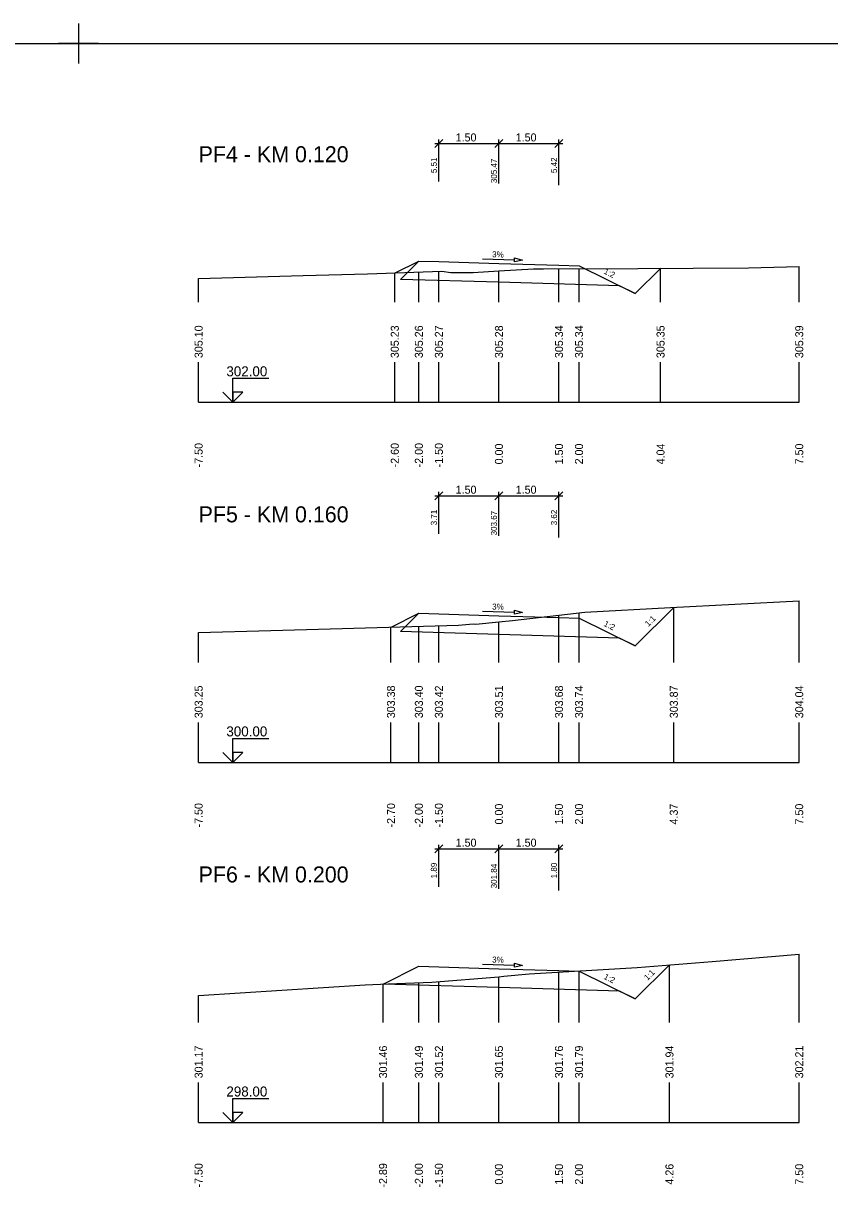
# Model space of a CAD drawing. Extents: x -5 to 1265, y -2 to 602.
# Drawn here: x 196.3 to 397.5, y 307.8 to 601.7 of the extents above; entities that cross this region are included whole.
import ezdxf

# ---------------------------------------------------------------- set-up
doc = ezdxf.new("R2010")
doc.units = 0
for name, color, linetype in [('KOTA', 7, 'Continuous'), ('KOTA_DELKY', 7, 'Continuous'), ('KOTA_DELKY_CONT', 7, 'Continuous'), ('NS_TELESO_VOZOVKY', 7, 'Continuous'), ('NS_V_PF', 7, 'Continuous'), ('REZY_PF_PUVODNI', 7, 'Continuous'), ('SESTAVY_REZU_PF', 7, 'Continuous'), ('SKLON', 7, 'Continuous'), ('SVK', 7, 'Continuous')]:
    doc.layers.add(name, color=color, linetype=linetype)

msp = doc.modelspace()

# ---------------------------------------------------------------- linework, layer by layer
for p, q in [((210, 601.67), (210, 591.67)), ((210, 601.67), (210, 591.67)), ((210, 601.67), (210, 591.67)), ((210, 601.67), (210, 591.67)), ((210, 601.67), (210, 591.67)), ((210, 601.67), (210, 591.67)), ((210, 601.67), (210, 591.67)), ((210, 601.67), (210, 591.67)), ((210, 601.67), (210, 591.67)), ((210, 601.67), (210, 591.67)), ((210, 601.67), (210, 591.67)), ((210, 601.67), (210, 591.67)), ((210, 601.67), (210, 591.67)), ((210, 601.67), (210, 591.67)), ((210, 601.67), (210, 591.67)), ((210, 601.67), (210, 591.67)), ((210, 601.67), (210, 591.67)), ((210, 601.67), (210, 591.67)), ((210, 601.67), (210, 591.67)), ((210, 601.67), (210, 591.67)), ((210, 601.67), (210, 591.67)), ((210, 601.67), (210, 591.67)), ((210, 601.67), (210, 591.67)), ((210, 601.67), (210, 591.67)), ((210, 601.67), (210, 591.67)), ((210, 601.67), (210, 591.67)), ((210, 601.67), (210, 591.67)), ((210, 601.67), (210, 591.67)), ((210, 601.67), (210, 591.67)), ((210, 601.67), (210, 591.67)), ((210, 601.67), (210, 591.67)), ((210, 601.67), (210, 591.67)), ((210, 601.67), (210, 591.67)), ((210, 601.67), (210, 591.67)), ((210, 601.67), (210, 591.67)), ((210, 601.67), (210, 591.67)), ((210, 601.67), (210, 591.67)), ((210, 601.67), (210, 591.67)), ((210, 601.67), (210, 591.67)), ((210, 601.67), (210, 591.67)), ((210, 601.67), (210, 591.67)), ((210, 601.67), (210, 591.67)), ((210, 601.67), (210, 591.67)), ((210, 601.67), (210, 591.67)), ((210, 601.67), (210, 591.67)), ((210, 601.67), (210, 591.67)), ((210, 601.67), (210, 591.67)), ((210, 601.67), (210, 591.67)), ((210, 601.67), (210, 591.67)), ((210, 601.67), (210, 591.67)), ((210, 601.67), (210, 591.67)), ((210, 601.67), (210, 591.67)), ((210, 601.67), (210, 591.67)), ((210, 601.67), (210, 591.67)), ((215, 596.67), (205, 596.67)), ((215, 596.67), (205, 596.67)), ((215, 596.67), (205, 596.67)), ((215, 596.67), (205, 596.67)), ((215, 596.67), (205, 596.67)), ((215, 596.67), (205, 596.67)), ((215, 596.67), (205, 596.67)), ((215, 596.67), (205, 596.67)), ((215, 596.67), (205, 596.67)), ((215, 596.67), (205, 596.67)), ((215, 596.67), (205, 596.67)), ((215, 596.67), (205, 596.67)), ((215, 596.67), (205, 596.67)), ((215, 596.67), (205, 596.67)), ((215, 596.67), (205, 596.67)), ((215, 596.67), (205, 596.67)), ((215, 596.67), (205, 596.67)), ((215, 596.67), (205, 596.67)), ((215, 596.67), (205, 596.67)), ((215, 596.67), (205, 596.67)), ((215, 596.67), (205, 596.67)), ((215, 596.67), (205, 596.67)), ((215, 596.67), (205, 596.67)), ((215, 596.67), (205, 596.67)), ((215, 596.67), (205, 596.67)), ((215, 596.67), (205, 596.67)), ((215, 596.67), (205, 596.67)), ((215, 596.67), (205, 596.67)), ((215, 596.67), (205, 596.67)), ((215, 596.67), (205, 596.67)), ((215, 596.67), (205, 596.67)), ((215, 596.67), (205, 596.67)), ((215, 596.67), (205, 596.67)), ((215, 596.67), (205, 596.67)), ((215, 596.67), (205, 596.67)), ((215, 596.67), (205, 596.67)), ((215, 596.67), (205, 596.67)), ((215, 596.67), (205, 596.67)), ((215, 596.67), (205, 596.67)), ((215, 596.67), (205, 596.67)), ((215, 596.67), (205, 596.67)), ((215, 596.67), (205, 596.67)), ((215, 596.67), (205, 596.67)), ((215, 596.67), (205, 596.67)), ((215, 596.67), (205, 596.67)), ((215, 596.67), (205, 596.67)), ((215, 596.67), (205, 596.67)), ((215, 596.67), (205, 596.67)), ((215, 596.67), (205, 596.67)), ((215, 596.67), (205, 596.67)), ((215, 596.67), (205, 596.67)), ((215, 596.67), (205, 596.67)), ((215, 596.67), (205, 596.67)), ((215, 596.67), (205, 596.67))]:
    msp.add_line(p, q)
msp.add_lwpolyline([(0, 596.67), (1260, 596.67), (1260, 2.67), (0, 2.67)], close=True)
at = {"layer": 'KOTA'}
for points in [[(248.51, 507), (246.01, 509.5), (248.51, 507), (248.51, 513), (257.51, 513)], [(248.51, 507), (251.01, 509.5), (248.51, 509.5), (248.51, 507)], [(248.51, 507), (251.01, 509.5), (248.51, 509.5)], [(248.51, 417), (246.01, 419.5), (248.51, 417), (248.51, 423), (257.51, 423)], [(248.51, 417), (251.01, 419.5), (248.51, 419.5), (248.51, 417)], [(248.51, 417), (251.01, 419.5), (248.51, 419.5)], [(248.51, 327), (246.01, 329.5), (248.51, 327), (248.51, 333), (257.51, 333)], [(248.51, 327), (251.01, 329.5), (248.51, 329.5), (248.51, 327)], [(248.51, 327), (251.01, 329.5), (248.51, 329.5)]]:
    msp.add_lwpolyline(points, dxfattribs=at)
at = {"layer": 'KOTA_DELKY'}
for points in [[(299, 570.7), (301, 572.7)], [(299, 571.7), (316, 571.7)], [(300, 562.15), (300, 572.7)], [(314, 570.7), (316, 572.7)], [(314, 570.7), (316, 572.7)], [(314, 571.7), (331, 571.7)], [(315, 561.7), (315, 572.7)], [(315, 561.7), (315, 572.7)], [(329, 570.7), (331, 572.7)], [(330, 561.25), (330, 572.7)], [(299, 482.66), (301, 484.66)], [(299, 483.66), (316, 483.66)], [(300, 474.11), (300, 484.66)], [(314, 482.66), (316, 484.66)], [(314, 482.66), (316, 484.66)], [(314, 483.66), (331, 483.66)], [(315, 473.66), (315, 484.66)], [(315, 473.66), (315, 484.66)], [(329, 482.66), (331, 484.66)], [(330, 473.21), (330, 484.66)], [(299, 394.44), (301, 396.44)], [(299, 395.44), (316, 395.44)], [(300, 385.89), (300, 396.44)], [(314, 394.44), (316, 396.44)], [(314, 394.44), (316, 396.44)], [(314, 395.44), (331, 395.44)], [(315, 385.44), (315, 396.44)], [(315, 385.44), (315, 396.44)], [(329, 394.44), (331, 396.44)], [(330, 384.99), (330, 396.44)]]:
    msp.add_lwpolyline(points, dxfattribs=at)
at = {"layer": 'NS_TELESO_VOZOVKY'}
for points in [[(315, 541.7), (330, 541.25), (335, 541.1), (349.01, 534.17), (345.11, 536.09), (315, 537), (290.44, 537.73), (295, 542.3), (300, 542.15), (315, 541.7)], [(315, 453.66), (330, 453.21), (335, 453.06), (349.01, 446.13), (345.11, 448.06), (315, 448.96), (290.44, 449.7), (295, 454.26), (300, 454.11), (315, 453.66)], [(315, 365.44), (330, 364.99), (335, 364.84), (349.01, 357.91), (345.11, 359.84), (315, 360.74), (286.13, 361.61), (295, 366.04), (300, 365.89), (315, 365.44)]]:
    msp.add_lwpolyline(points, dxfattribs=at)
at = {"layer": 'NS_V_PF'}
for points in [[(289.1, 539.35), (295, 542.3), (300, 542.15), (315, 541.7), (330, 541.25), (335, 541.1), (349.01, 534.17), (355.42, 540.51)], [(288.1, 450.81), (295, 454.26), (300, 454.11), (315, 453.66), (330, 453.21), (335, 453.06), (349.01, 446.13), (358.71, 455.73)], [(286.05, 361.57), (295, 366.04), (300, 365.89), (315, 365.44), (330, 364.99), (335, 364.84), (349.01, 357.91), (357.58, 366.39)]]:
    msp.add_lwpolyline(points, dxfattribs=at)
at = {"layer": 'REZY_PF_PUVODNI'}
for points in [[(240, 537.97), (266.07, 538.67), (282.21, 539.11), (300.73, 539.76), (302.98, 539.48), (308.56, 539.48), (315, 539.84), (315, 539.84), (323.66, 540.33), (326.17, 540.39), (349.65, 540.48), (377.36, 540.59), (390, 540.94)], [(240, 449.5), (258, 449.95), (275.82, 450.46), (304.88, 451.29), (308.54, 451.6), (309.27, 451.54), (315, 452.12), (315, 452.12), (318.41, 452.47), (336.49, 454.58), (357.82, 455.68), (390, 457.35)], [(240, 358.74), (281.56, 361.38), (287.32, 361.62), (298.21, 362.07), (315, 363.45), (315, 363.45), (316.2, 363.55), (322.52, 364.15), (349.49, 365.72), (368.23, 367.28), (390, 369.1)]]:
    msp.add_lwpolyline(points, dxfattribs=at)
at = {"layer": 'SESTAVY_REZU_PF'}
for points in [[(240, 507), (390, 507)], [(240, 417), (390, 417)], [(240, 327), (390, 327)]]:
    msp.add_lwpolyline(points, dxfattribs=at)
at = {"layer": 'SKLON'}
for points in [[(310.92, 542.82), (318.91, 542.58)], [(318.93, 543.08), (320.91, 542.52), (318.9, 542.08), (318.93, 543.08)], [(310.92, 454.78), (318.91, 454.55)], [(318.93, 455.04), (320.91, 454.49), (318.9, 454.05), (318.93, 455.04)], [(310.92, 366.56), (318.91, 366.32)], [(318.93, 366.82), (320.91, 366.26), (318.9, 365.82), (318.93, 366.82)]]:
    msp.add_lwpolyline(points, dxfattribs=at)
for points in [[(318.93, 543.08), (320.91, 542.52), (318.9, 542.08)], [(318.93, 455.04), (320.91, 454.49), (318.9, 454.05)], [(318.93, 366.82), (320.91, 366.26), (318.9, 365.82)]]:
    msp.add_lwpolyline(points, close=True, dxfattribs=at)
at = {"layer": 'SVK'}
for points in [[(390, 532), (390, 540.94)], [(240, 532), (240, 537.97)], [(288.99, 532), (288.99, 539.34)], [(295, 532), (295, 539.56)], [(300, 532), (300, 539.73)], [(315, 532), (315, 539.84)], [(330, 532), (330, 540.41)], [(335, 532), (335, 540.43)], [(355.36, 532), (355.36, 540.51)], [(240, 507), (240, 517)], [(288.99, 507), (288.99, 517)], [(295, 507), (295, 517)], [(300, 507), (300, 517)], [(315, 507), (315, 517)], [(330, 507), (330, 517)], [(335, 507), (335, 517)], [(355.36, 507), (355.36, 517)], [(390, 507), (390, 517)], [(358.67, 442), (358.67, 455.73)], [(390, 442), (390, 457.35)], [(330, 442), (330, 453.82)], [(335, 442), (335, 454.4)], [(288.04, 442), (288.04, 450.81)], [(295, 442), (295, 451.01)], [(300, 442), (300, 451.15)], [(315, 442), (315, 452.12)], [(240, 442), (240, 449.5)], [(240, 417), (240, 427)], [(288.04, 417), (288.04, 427)], [(295, 417), (295, 427)], [(300, 417), (300, 427)], [(315, 417), (315, 427)], [(330, 417), (330, 427)], [(335, 417), (335, 427)], [(358.67, 417), (358.67, 427)], [(390, 417), (390, 427)], [(390, 352), (390, 369.1)], [(330, 352), (330, 364.59)], [(335, 352), (335, 364.88)], [(357.59, 352), (357.59, 366.39)], [(286.06, 352), (286.06, 361.57)], [(295, 352), (295, 361.94)], [(300, 352), (300, 362.22)], [(315, 352), (315, 363.45)], [(240, 352), (240, 358.74)], [(240, 327), (240, 337)], [(286.06, 327), (286.06, 337)], [(295, 327), (295, 337)], [(300, 327), (300, 337)], [(315, 327), (315, 337)], [(330, 327), (330, 337)], [(335, 327), (335, 337)], [(357.59, 327), (357.59, 337)], [(390, 327), (390, 337)]]:
    msp.add_lwpolyline(points, dxfattribs=at)

# ---------------------------------------------------------------- texts
at = {"layer": 'KOTA'}
for s, p in [('302.00', (246.93, 513.5)), ('300.00', (246.93, 423.5)), ('298.00', (246.93, 333.5))]:
    msp.add_text(s, height=2.5, dxfattribs=at).set_placement(p)
at = {"layer": 'KOTA_DELKY'}
for p in [(304.19, 572.2), (319.19, 572.2), (304.19, 484.16), (319.19, 484.16), (304.19, 395.94), (319.19, 395.94)]:
    msp.add_text('1.50', height=2, dxfattribs=at).set_placement(p)
at = {"layer": 'KOTA_DELKY_CONT'}
for s, p in [('5.51', (299.5, 564.29)), ('305.47', (314.5, 561.77)), ('5.42', (329.5, 564.29)), ('3.71', (299.5, 476.25)), ('303.67', (314.5, 473.74)), ('3.62', (329.5, 476.25)), ('1.89', (299.5, 388.03)), ('301.84', (314.5, 385.52)), ('1.80', (329.5, 388.03))]:
    msp.add_text(s, height=1.5, rotation=90, dxfattribs=at).set_placement(p)
at = {"layer": 'SESTAVY_REZU_PF'}
for s, p in [('PF4 - KM 0.120', (240, 567)), ('PF5 - KM 0.160', (240, 477)), ('PF6 - KM 0.200', (240, 387))]:
    msp.add_text(s, height=4, dxfattribs=at).set_placement(p)
at = {"layer": 'SKLON'}
for s, rotation, p in [('3%', 358.2816, (313.29, 543.25)), ('1:2', 333.679, (341.04, 539.23)), ('3%', 358.2816, (313.29, 455.21)), ('1:1', 44.7149, (352.33, 450.83)), ('1:2', 333.679, (341.04, 451.19)), ('3%', 358.2816, (313.29, 366.99)), ('1:1', 44.7149, (352.1, 362.37)), ('1:2', 333.679, (341.04, 362.97))]:
    msp.add_text(s, height=1.5, rotation=rotation, dxfattribs=at).set_placement(p)
at = {"layer": 'SVK'}
for s, p in [(' 305.10', (241, 517.3)), (' 305.23', (289.99, 517.3)), (' 305.26', (296, 517.3)), (' 305.27', (301, 517.3)), (' 305.28', (316, 517.3)), (' 305.34', (331, 517.3)), (' 305.34', (336, 517.3)), (' 305.35', (356.36, 517.3)), (' 305.39', (391, 517.3)), (' -7.50', (241, 490)), (' -2.60', (289.99, 490)), (' -2.00', (296, 490)), (' -1.50', (301, 490)), ('  0.00', (316, 490)), ('  1.50', (331, 490)), ('  2.00', (336, 490)), ('  4.04', (356.36, 490)), ('  7.50', (391, 490)), (' 303.25', (241, 427.3)), (' 303.38', (289.04, 427.3)), (' 303.40', (296, 427.3)), (' 303.42', (301, 427.3)), (' 303.51', (316, 427.3)), (' 303.68', (331, 427.3)), (' 303.74', (336, 427.3)), (' 303.87', (359.67, 427.3)), (' 304.04', (391, 427.3)), (' -7.50', (241, 400)), (' -2.70', (289.04, 400)), (' -2.00', (296, 400)), (' -1.50', (301, 400)), ('  0.00', (316, 400)), ('  1.50', (331, 400)), ('  2.00', (336, 400)), ('  4.37', (359.67, 400)), ('  7.50', (391, 400)), (' 301.17', (241, 337.3)), (' 301.46', (287.06, 337.3)), (' 301.49', (296, 337.3)), (' 301.52', (301, 337.3)), (' 301.65', (316, 337.3)), (' 301.76', (331, 337.3)), (' 301.79', (336, 337.3)), (' 301.94', (358.59, 337.3)), (' 302.21', (391, 337.3)), (' -7.50', (241, 310)), (' -2.89', (287.06, 310)), (' -2.00', (296, 310)), (' -1.50', (301, 310)), ('  0.00', (316, 310)), ('  1.50', (331, 310)), ('  2.00', (336, 310)), ('  4.26', (358.59, 310)), ('  7.50', (391, 310))]:
    msp.add_text(s, height=2, rotation=90, dxfattribs=at).set_placement(p)

doc.saveas('drawing.dxf')
